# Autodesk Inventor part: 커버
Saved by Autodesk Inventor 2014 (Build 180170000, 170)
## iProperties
Created: 2025-02
Part Number: 커버
Material: 알루미늄 6061
Document SubType Name: Modeling
Designer: dg
Density: 2.71 g/cm^3
Appearance: 알루미늄 - 평지
Mass: 271.542 g
Surface Area: 388.647 cm^2
Volume: 100.2 cm^3
Author: jhkim
Creation Date: 2025-01-06
Sending System: Autodesk Inventor 2025
Preprocessor: ST-DEVELOPER v20
Author: dg
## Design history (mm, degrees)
node "커버1"
node "솔리드1"
node "기준1"
